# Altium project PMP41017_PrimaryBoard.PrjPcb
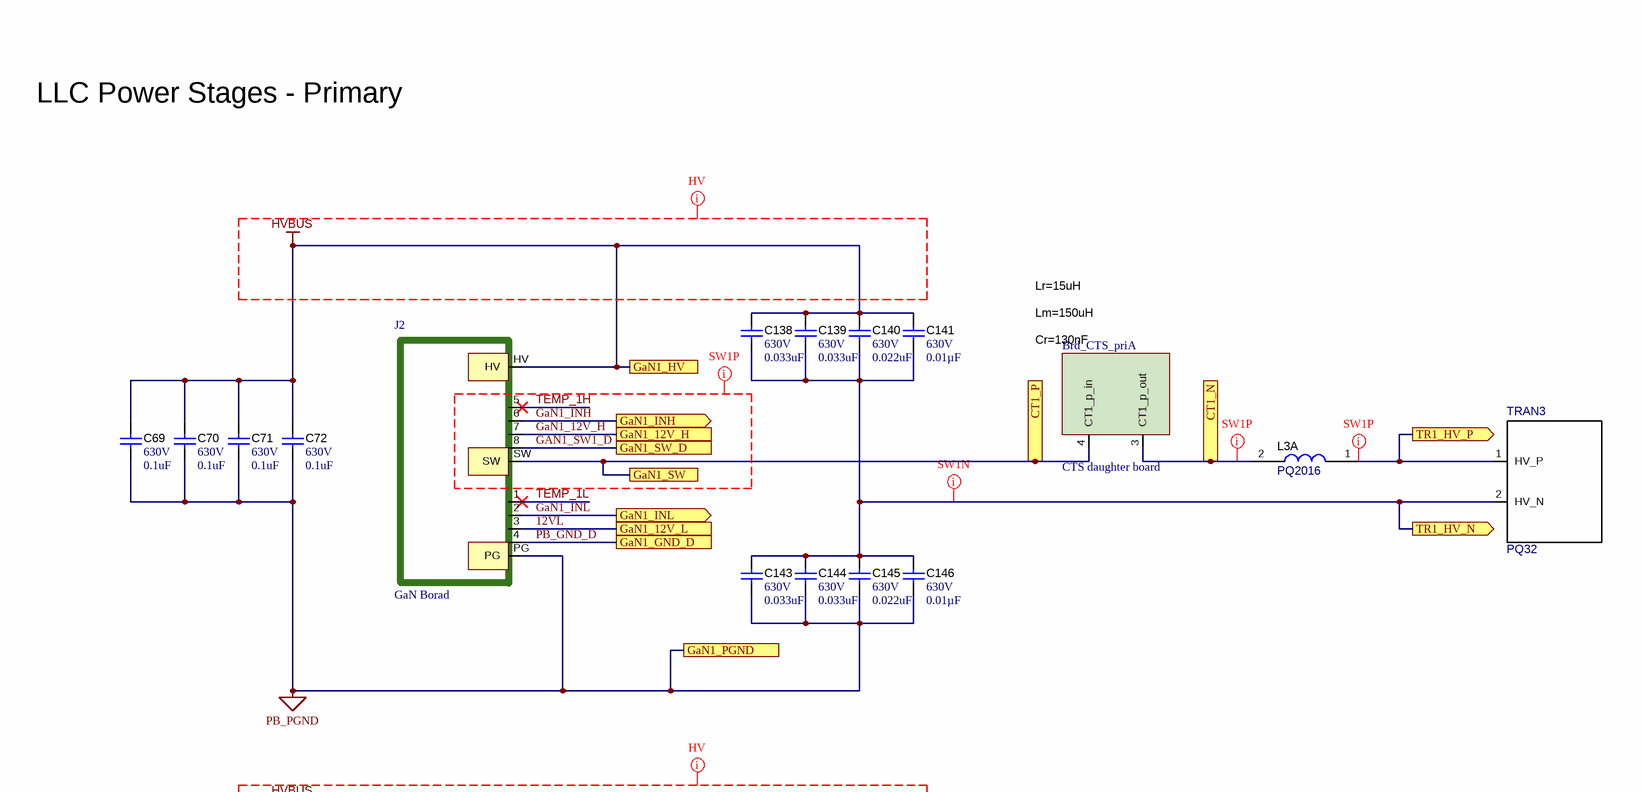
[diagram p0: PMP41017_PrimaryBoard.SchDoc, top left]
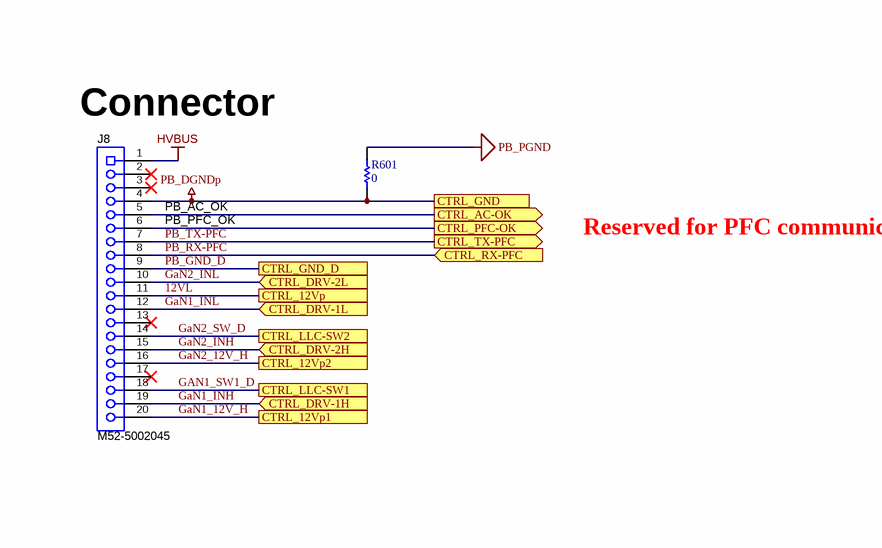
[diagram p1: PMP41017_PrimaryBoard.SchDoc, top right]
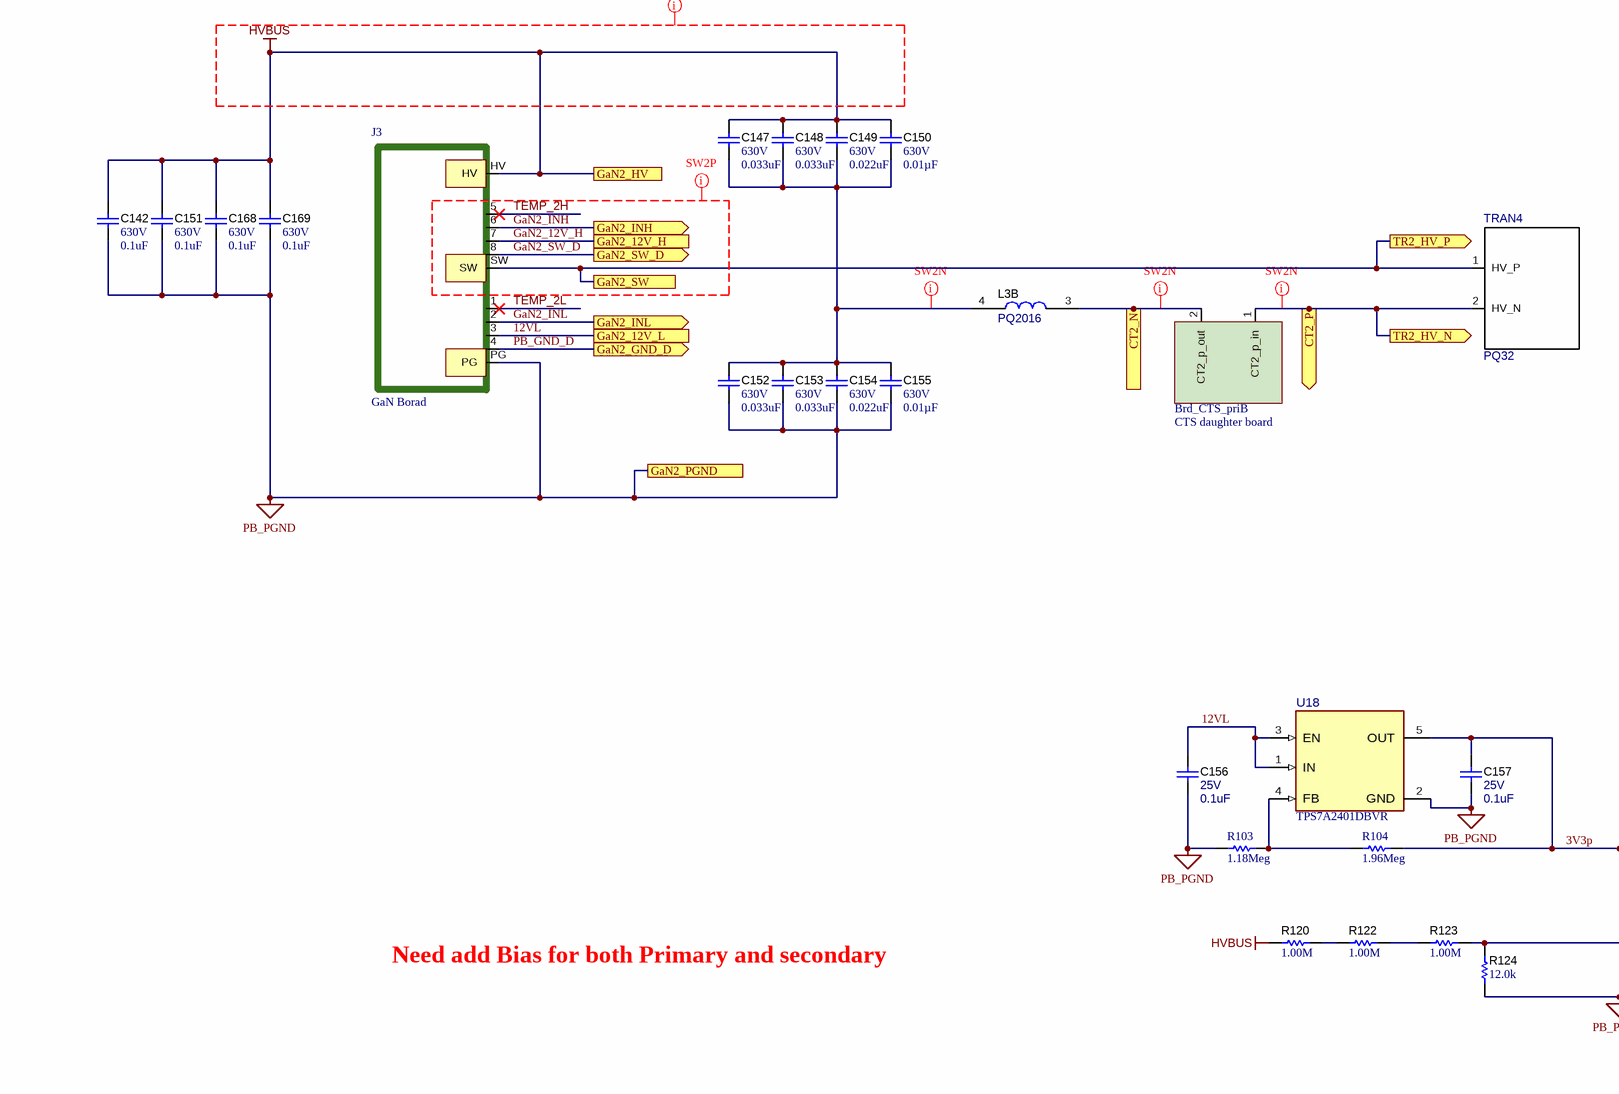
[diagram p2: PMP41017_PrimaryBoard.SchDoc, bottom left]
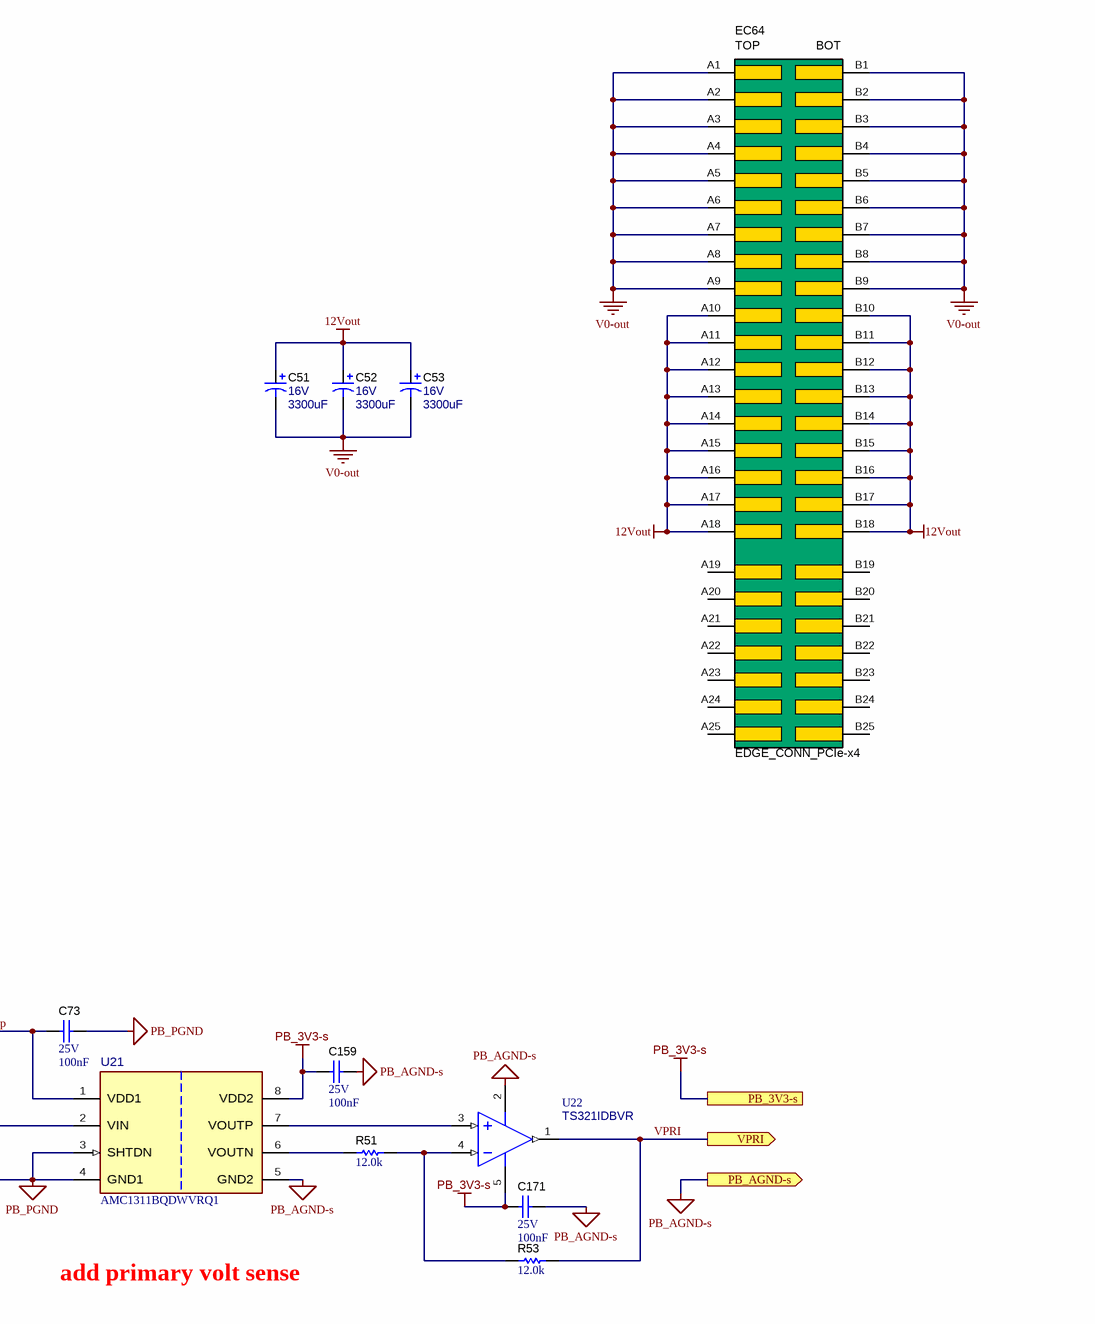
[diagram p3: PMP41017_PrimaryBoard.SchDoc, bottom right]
CopyrightYear: 2022; PCB_Layout: Desheng Guo; PCB_Rev: E1; PRJ_Customer: Public Release; PRJ_Engineer: Desheng Guo; PRJ_Number: PMP41017; PRJ_Title: CRPS 12V 3000W LLC; SCH_Rev: E1; TechSupport: http://www.ti.com/support; TID: N/A
1 sheet, 52 parts. Net scope: flat (ports and power ports of the same name join across sheets).
Board file: PMP41017_PrimaryBoard_Cyntec.PcbDoc

## Sheet PMP41017_PrimaryBoard.SchDoc
size A2; Date: Not shown in title block; ApprovedBy: Not shown in title block; CheckedBy: Not shown in title block; Author: Not shown in title block; CompanyName: Not shown in title block; Engineer: Not shown in title block; Organization: Not shown in title block; Address1: Not shown in title block; Address2: Not shown in title block; Address3: Not shown in title block; Address4: Not shown in title block; DocumentNumber: 1; Revision: Use project parameter SCH_Rev; SheetNumber: 1; SheetTotal: 1; PageSetup: Record=PageOptions¦CenterHorizontal=True¦CenterVertical=True¦PrintScale=0.69¦XCorrection=1.00¦YCorrection=1.00¦PrintKind=0¦BorderSize=5000000¦LeftOffset=0¦BottomOffset=0¦Orientation=2¦PaperLength=1000¦PaperWidth=1000¦Scale=100¦PaperSource=15¦PrintQuality=600¦MediaType=1¦DitherType=10¦PaperKind=Letter¦PrintScaleMode=1

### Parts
Brd_CTS_pri  CTS daughter board  [DB_PMP41017_CST]  (parts A,B of 2)
C51  VDC_V: 16V  ValueDisplayed: 3300uF  [860020378023]  (hidden comment: 860020378023)
C52  VDC_V: 16V  ValueDisplayed: 3300uF  [860020378023]  (hidden comment: 860020378023)
C53  VDC_V: 16V  ValueDisplayed: 3300uF  [860020378023]  (hidden comment: 860020378023)
C69  VDC_V: 630V  ValueDisplayed: 0.1uF  [1210_200]  (hidden comment: CGA6L1X7T2J104K160AC)
C70  VDC_V: 630V  ValueDisplayed: 0.1uF  [1210_200]  (hidden comment: CGA6L1X7T2J104K160AC)
C71  VDC_V: 630V  ValueDisplayed: 0.1uF  [1210_200]  (hidden comment: CGA6L1X7T2J104K160AC)
C72  VDC_V: 630V  ValueDisplayed: 0.1uF  [1210_200]  (hidden comment: CGA6L1X7T2J104K160AC)
C73  VDC_V: 25V  Cap_F: 100nF  [0603]  (hidden comment: GCM188R71E104KA57D)
C138  VDC_V: 630V  ValueDisplayed: 0.033uF  [1210_280]  (hidden comment: C3225C0G2J333J250AA)
C139  VDC_V: 630V  ValueDisplayed: 0.033uF  [1210_280]  (hidden comment: C3225C0G2J333J250AA)
C140  VDC_V: 630V  ValueDisplayed: 0.022uF  [1210_250]  (hidden comment: CGA6N4NP02J223J230AA)
C141  VDC_V: 630V  ValueDisplayed: 0.01µF  [1210_150]  (hidden comment: CGA6J4C0G2J103J125AA)
C142  VDC_V: 630V  ValueDisplayed: 0.1uF  [1210_200]  (hidden comment: CGA6L1X7T2J104K160AC)
C143  VDC_V: 630V  ValueDisplayed: 0.033uF  [1210_280]  (hidden comment: C3225C0G2J333J250AA)
C144  VDC_V: 630V  ValueDisplayed: 0.033uF  [1210_280]  (hidden comment: C3225C0G2J333J250AA)
C145  VDC_V: 630V  ValueDisplayed: 0.022uF  [1210_250]  (hidden comment: CGA6N4NP02J223J230AA)
C146  VDC_V: 630V  ValueDisplayed: 0.01µF  [1210_150]  (hidden comment: CGA6J4C0G2J103J125AA)
C147  VDC_V: 630V  ValueDisplayed: 0.033uF  [1210_280]  (hidden comment: C3225C0G2J333J250AA)
C148  VDC_V: 630V  ValueDisplayed: 0.033uF  [1210_280]  (hidden comment: C3225C0G2J333J250AA)
C149  VDC_V: 630V  ValueDisplayed: 0.022uF  [1210_250]  (hidden comment: CGA6N4NP02J223J230AA)
C150  VDC_V: 630V  ValueDisplayed: 0.01µF  [1210_150]  (hidden comment: CGA6J4C0G2J103J125AA)
C151  VDC_V: 630V  ValueDisplayed: 0.1uF  [1210_200]  (hidden comment: CGA6L1X7T2J104K160AC)
C152  VDC_V: 630V  ValueDisplayed: 0.033uF  [1210_280]  (hidden comment: C3225C0G2J333J250AA)
C153  VDC_V: 630V  ValueDisplayed: 0.033uF  [1210_280]  (hidden comment: C3225C0G2J333J250AA)
C154  VDC_V: 630V  ValueDisplayed: 0.022uF  [1210_250]  (hidden comment: CGA6N4NP02J223J230AA)
C155  VDC_V: 630V  ValueDisplayed: 0.01µF  [1210_150]  (hidden comment: CGA6J4C0G2J103J125AA)
C156  VDC_V: 25V  ValueDisplayed: 0.1uF  [0603]  (hidden comment: C1608X7R1E104K080AA)
C157  VDC_V: 25V  ValueDisplayed: 0.1uF  [0603]  (hidden comment: C1608X7R1E104K080AA)
C159  VDC_V: 25V  Cap_F: 100nF  [0603]  (hidden comment: GCM188R71E104KA57D)
C168  VDC_V: 630V  ValueDisplayed: 0.1uF  [1210_200]  (hidden comment: CGA6L1X7T2J104K160AC)
C169  VDC_V: 630V  ValueDisplayed: 0.1uF  [1210_200]  (hidden comment: CGA6L1X7T2J104K160AC)
C171  VDC_V: 25V  Cap_F: 100nF  [0603]  (hidden comment: GCM188R71E104KA57D)
EC64  EDGE_CONN_PCIe-x4  [EC_10035388-102LF]  (no BOM)
J2  GaN Borad  [DB_PMP41017_GAN]  (no BOM)
J3  GaN Borad  [DB_PMP41017_GAN]  (no BOM)
J8  M52-5002045  [M52-5002045]  (no BOM)
L3  PQ2016  [CHOKE-PQ2016 - H]  (parts A,B of 2)
R51  ValueDisplayed: 12.0k  [0603]  (hidden comment: RC0603FR-0712KL)
R53  ValueDisplayed: 12.0k  [0603]  (hidden comment: RC0603FR-0712KL)
R103  value 1.18Meg  [0402]
R104  value 1.96Meg  [0402]
R120  ValueDisplayed: 1.00M  [1206]  (hidden comment: CRCW12061M00FKEA)
R122  ValueDisplayed: 1.00M  [1206]  (hidden comment: CRCW12061M00FKEA)
R123  ValueDisplayed: 1.00M  [1206]  (hidden comment: CRCW12061M00FKEA)
R124  ValueDisplayed: 12.0k  [0603]  (hidden comment: RC0603FR-0712KL)
R601  value 0  [0402]
TRAN3  PQ32  [PQ3220-1500-400V12V_pri]
TRAN4  PQ32  [PQ3220-1500-400V12V_pri]
U18  TPS7A2401DBVR  [DBV0005A-MFG]
U21  AMC1311BQDWVRQ1  [DWV0008A-MFG]
U22  TS321IDBVR  [DBV0005A_L]

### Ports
CT1_N (out), CT1_P (out), CT2_N (out), CT2_P (out), CTRL_12Vp, CTRL_12Vp1, CTRL_12Vp2, CTRL_AC-OK (out), CTRL_DRV-1H (in), CTRL_DRV-1L (in), CTRL_DRV-2H (in), CTRL_DRV-2L (in), CTRL_GND, CTRL_GND_D, CTRL_LLC-SW1, CTRL_LLC-SW2, CTRL_PFC-OK (out), CTRL_RX-PFC (in), CTRL_TX-PFC (out), GaN1_12V_H, GaN1_12V_L, GaN1_GND_D, GaN1_HV, GaN1_INH (out), GaN1_INL (out), GaN1_PGND, GaN1_SW, GaN1_SW_D, GaN2_12V_H, GaN2_12V_L, GaN2_GND_D (out), GaN2_HV, GaN2_INH (out), GaN2_INL (out), GaN2_PGND, GaN2_SW, GaN2_SW_D (out), PB_3V3-s, PB_AGND-s (out), TR1_HV_N (out), TR1_HV_P (out), TR2_HV_N (out), TR2_HV_P (out), VPRI (out)

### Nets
12Vout: C51.1(+) C52.1(+) C53.1(+) EC64.A10 EC64.A11 EC64.A12 EC64.A13 EC64.A14 EC64.A15 EC64.A16 EC64.A17 EC64.A18 EC64.B10 EC64.B11 EC64.B12 EC64.B13 EC64.B14 EC64.B15 EC64.B16 EC64.B17 EC64.B18
HVBUS: C69.1 C70.1 C71.1 C72.1 C138.1 C139.1 C140.1 C141.1 C142.1 C147.1 C148.1 C149.1 C150.1 C151.1 C168.1 C169.1 J2.HV J3.HV J8.1 R120.2 ; port GaN1_HV, port GaN2_HV
PB_3V3-s: C159.1 C171.1 U21.8(VDD2) U22.5(VCC+) ; port PB_3V3-s
PB_AGND-s: C159.2 C171.2 U21.5(GND2) U22.2(VCC-) ; port PB_AGND-s
PB_DGNDp: J8.4 R601.2 ; port CTRL_GND
PB_PGND: C69.2 C70.2 C71.2 C72.2 C73.2 C142.2 C143.2 C144.2 C145.2 C146.2 C151.2 C152.2 C153.2 C154.2 C155.2 C156.2 C157.2 C168.2 C169.2 J2.PG J3.PG R103.1 R124.1 R601.1 U18.2(GND) U21.3(SHTDN) U21.4(GND1) ; port GaN1_PGND, port GaN2_PGND
V0-out: C51.2(-) C52.2(-) C53.2(-) EC64.A1 EC64.A2 EC64.A3 EC64.A4 EC64.A5 EC64.A6 EC64.A7 EC64.A8 EC64.A9 EC64.B1 EC64.B2 EC64.B3 EC64.B4 EC64.B5 EC64.B6 EC64.B7 EC64.B8 EC64.B9
3V3p: C73.1 C157.1 R104.2 U18.5(OUT) U21.1(VDD1)  [project net 3V3p_1]
12VL: C156.1 J2.3 J3.3 J8.11 U18.1(IN) U18.3(EN) ; port GaN1_12V_L, port CTRL_12Vp, port GaN2_12V_L
CT1_N: Brd_CTS_pri.3(CT1_p_out) L3.2 ; port CT1_N
CT1_P: Brd_CTS_pri.4(CT1_p_in) J2.SW ; port GaN1_SW, port CT1_P
CT2_N: Brd_CTS_pri.2(CT2_p_out) L3.3 ; port CT2_N
CT2_P: Brd_CTS_pri.1(CT2_p_in) TRAN4.2(HV_N) ; port CT2_P, port TR2_HV_N
GaN1_12V_H: J2.7 J8.20 ; port GaN1_12V_H, port CTRL_12Vp1
GaN1_INH: J2.6 J8.19 ; port GaN1_INH, port CTRL_DRV-1H
GaN1_INL: J2.2 J8.12 ; port GaN1_INL, port CTRL_DRV-1L
GAN1_SW1_D: J2.8 J8.18 ; port CTRL_LLC-SW1, port GaN1_SW_D
GaN2_12V_H: J3.7 J8.16 ; port CTRL_12Vp2, port GaN2_12V_H
GaN2_INH: J3.6 J8.15 ; port CTRL_DRV-2H, port GaN2_INH
GaN2_INL: J3.2 J8.10 ; port CTRL_DRV-2L, port GaN2_INL
GaN2_SW: J3.SW TRAN4.1(HV_P) ; port GaN2_SW, port TR2_HV_P
GaN2_SW_D: J3.8 J8.14 ; port CTRL_LLC-SW2, port GaN2_SW_D
PB_AC_OK: J8.5 ; port CTRL_AC-OK
PB_GND_D: J2.4 J3.4 J8.9 ; port GaN1_GND_D, port CTRL_GND_D, port GaN2_GND_D
PB_PFC_OK: J8.6 ; port CTRL_PFC-OK
PB_RX-PFC: J8.8 ; port CTRL_RX-PFC
PB_TX-PFC: J8.7 ; port CTRL_TX-PFC
TEMP_1H: J2.5  [project net TEMP_1H_1]
TEMP_1L: J2.1  [project net TEMP_1L_1]
TEMP_2H: J3.5  [project net TEMP_2H_1]
TEMP_2L: J3.1  [project net TEMP_2L_1]
TR1_HV_N: C138.2 C139.2 C140.2 C141.2 C143.1 C144.1 C145.1 C146.1 TRAN3.2(HV_N) ; port TR1_HV_N
TR1_HV_P: L3.1 TRAN3.1(HV_P) ; port TR1_HV_P
VPRI: R53.1 U22.1(OUT) ; port VPRI
NetC147_2: C147.2 C148.2 C149.2 C150.2 C152.1 C153.1 C154.1 C155.1 L3.4
NetR51_1: R51.1 R53.2 U22.4(IN-)
NetR51_2: R51.2 U21.6(VOUTN)
NetR103_2: R103.2 R104.1 U18.4(FB)
NetR120_1: R120.1 R122.2
NetR122_1: R122.1 R123.2
NetR123_1: R123.1 R124.2 U21.2(VIN)
NetU21_7: U21.7(VOUTP) U22.3(IN+)

Not connected (* = marked no-connect by the designer): EC64 A19 A20 A21 A22 A23 A24 A25 B19 B20 B21 B22 B23 B24 B25; J8 2* 3* 13* 17*

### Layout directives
net class SW1P: CT1_N, GaN1_12V_H, GaN1_INH, GAN1_SW1_D, TEMP_1H, TR1_HV_P
net class SW1N: TR1_HV_N
net class HV: HVBUS
net class SW2P: GaN2_12V_H, GaN2_INH, GaN2_SW_D, TEMP_2H
net class SW2N: CT2_N, CT2_P, NetC147_2

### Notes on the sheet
- (near J8) Connector
- LLC Power Stages - Primary
- Reserved for PFC communication
- Lm=150uH
- Lr=15uH
- Cr=130nF
- Need add Bias for both Primary and secondary
- add primary volt sense

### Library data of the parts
Brd_CTS_pri = Board_CTS
C51-C53 = Cap_Polarized_1: CAP, AL, 3300 uF, 16 V, +/- 20%, 0.023 ohm, TH; Manufacturer: Würth Elektronik; TaMin_C: -40°C; ESR_ohm: 0.034; Polarized: Y; SizeAreaWB_mm2: 324; Value1: 0.034 ohm; U/M: EA; Value: 3300uF; TaMax_C: 105°C; SizeZ_mm: 33.5; SizeX_mm: 13; Cap_Case: 13x25mm; SizeArea_mm2: 256; CompType: Capacitor; Cap_F: 3.3mF; IRMS_A: 3.16A; AEC Grade: 1; AEC Category: Q200
C69-C72 C142 C151 C168 C169 = CMP-0009140-2: CAP, CERM, 0.1 uF, 630 V, +/- 10%, X7R, AEC-Q200 Grade 1, 1210; Manufacturer: TDK; TaMin_C: -55°C; Polarized: N; SizeAreaWB_mm2: 14.7; Value1: Unknown; U/M: EA; Value: 0.1uF; TaMax_C: 125°C; SizeZ_mm: 2; SizeX_mm: 3.2; SizeY_mm: 2.5; Cap_Case: 1210; SizeArea_mm2: 8; AEC Qualified: Y; Cap_F: 100nF; AEC Grade: 1; AEC Category: Q200
C73 C159 C171 = CMP-0084679-1: CAP, CERM, 0.1 µF, 25 V,+/- 10%, X7R, AEC-Q200 Grade 1, 0603; Manufacturer: MuRata; TaMin_C: -55°C; SizeY_mm: 0.8; Polarized: N; SizeArea_mm2: 1.28; SizeZ_mm: 1; SizeX_mm: 1.6; AEC Qualified: Y; AEC Category: Q200; Value: 0.1uF; ValueDisplayed: 0.1µF; TaMax_C: 125°C; U/M: EA; SizeAreaWB_mm2: 4.68
C138 C139 C143 C144 C147 C148 C152 C153 = CMP-0009097-2: CAP, CERM, 0.033 uF, 630 V, +/- 5%, C0G/NP0, 1210; Manufacturer: TDK; TaMin_C: -55°C; Polarized: N; SizeAreaWB_mm2: 14.7; Value1: Unknown; U/M: EA; TaMax_C: 125°C; SizeZ_mm: 2.8; SizeX_mm: 3.2; SizeY_mm: 2.5; Cap_Case: 1210; SizeArea_mm2: 8; Cap_F: 33nF; AEC Category: Q200
C140 C145 C149 C154 = CMP-0009153-2: CAP, CERM, 0.022 uF, 630 V, +/- 5%, C0G/NP0, AEC-Q200 Grade 0,; Manufacturer: TDK; TaMin_C: -55°C; Polarized: N; SizeAreaWB_mm2: 14.7; Value1: Unknown; U/M: EA; TaMax_C: 150°C; SizeZ_mm: 2.5; SizeX_mm: 3.2; Cap_Case: 1210; SizeArea_mm2: 8; AEC Qualified: Y; Cap_F: 22nF; AEC Grade: 0; AEC Category: Q200
C141 C146 C150 C155 = CMP-0860380-1: CAP, CERM, 0.01 µF, 630 V,+/- 5%, C0G/NP0, AEC-Q200 Grade 1, 1210; Manufacturer: TDK; AEC Qualified: Y; Polarized: N; SizeZ_mm: 1.5; SizeArea_mm2: 8; U/M: EA; SizeX_mm: 3.2; SizeY_mm: 2.5; Cap_F: 10nF; SizeAreaWB_mm2: 14.7; TaMin_C: -55°C; Cap_Case: 1210; Value: 0.01uF; AEC Grade: 1; TaMax_C: 125°C; AEC Category: Q200
C156 C157 = CMP-0007039-5: CAP, CERM, 0.1 uF, 25 V, +/- 10%, X7R, 0603; Manufacturer: TDK; TaMin_C: -55°C; Polarized: N; SizeAreaWB_mm2: 4.68; Value1: Unknown; U/M: EA; Value: 0.1uF; TaMax_C: 125°C; SizeZ_mm: 1; SizeX_mm: 1.6; SizeY_mm: 0.8; SizeArea_mm2: 1.28; Cap_F: 100nF; AEC Category: Q200
EC64 = EDGE_CONN_CRPS: Card Edge Footprint for CRPS Server PSU, 2.54mm, 25x2; Manufacturer: Texas Instruments
J2 J3 = Brd_GaN_footprint
J8 = Receptacle_20x1: Receptacle, 20x1, 1.27mm, TH; Manufacturer: Harwin Inc.; CT: False; CompType: Socket
L3 = INDUCTOR_COUPLED: Customized Resonant Choke; Manufacturer: YAXIN ELECTRONIC TECH; PartNumber: YXS50494T; DCR_ohm: 0.019; CompType: Coupled Inductor; Ind_H: 13uH; SizeX_mm: 22; SizeY_mm: 10; SizeZ_mm: 16
R51 R53 R124 = CMP-0022779-5: RES, 12.0 k, 1%, 0.1 W, 0603; Manufacturer: Yageo; Power_W: 100mW; TempCo: 100 ppm/C; Value_Code: 12k0; Value: 12.0k; Res_ohm: 12k; SizeX_mm: 1.6; SizeY_mm: 0.8; SizeZ_mm: 1; Value2: 0.1W; SizeArea_mm2: 1.28; AEC Qualified: N; VDC_V: 75V; AEC Category: Q200; SizeAreaWB_mm2: 4.68
R103 = Res1: RES, 1.18Meg, 1%, 0.1 W, 0402
R104 = Res1: RES, 1.96Meg, 1%, 0.1 W, 0402
R120 R122 R123 = CMP-0016716-3: RES, 1.00 M, 1%, 0.25 W, AEC-Q200 Grade 0, 1206; Manufacturer: Vishay-Dale; Power_W: 250mW; TempCo: 100 ppm/C; Value_Code: 1M00; Value: 1.00Meg; EIA_Code: E96; Res_ohm: 1M; SizeX_mm: 3.2; SizeY_mm: 1.6; SizeZ_mm: 1.35; Value2: 0.25W; SizeArea_mm2: 5.12; AEC Qualified: Y; VDC_V: 200V; AEC Category: Q200; AEC Grade: 0
R601 = Res1: RES, 0, 5%, 0.1 W, AEC-Q200 Grade 0, 0402
TRAN3 TRAN4 = Transformer_pri: PQ32 TRANSFORMER; Manufacturer: YAXIN ELECTRONIC TECH; SymbolCreator: Use LDAP id; SymbolVersion: use current date i.e. 2008-05-20
U18 = CMP-0089843-1: Linear Voltage Regulator IC 1 Output 200mA SOT-23-5; Manufacturer: Texas Instruments; Output Type: AdjustableProgrammable; Accuracy Percentage: 2%; AEC Qualified: No; Max Supply Voltage: 18V; Dropout Voltage: 160mV; SizeZ_mm: 1.45mm; Output Voltage: 1.24-17.75V; Min Supply Voltage: 2.4V; TJmax_C: +125°C; Nominal Supply Current: 2uA; Number Of Outputs: 1; Standoff Height: 0mm
U21 = CMP-0090465-1: Automotive 2-V input, reinforced isolated amplifier with high CMTI for voltage sensing 8-SOIC -40 to 125; Manufacturer: Texas Instruments; Input Offset Voltage: -1.1mV; Response Time: 50us; Standoff Height: 0.36mm; Nominal Supply Current: 5.3-7.1mA; AEC Grade: Grade 1; Number Of Channels: 1; TJmax_C: +150°C; AEC Qualified: Yes; Max Supply Voltage: 5.5V; SizeZ_mm: 2.8mm; Input Bias Current: 0.0035uA; TaMax_C: +125°C; TaMin_C: -40°C; Output Current Per Channel: 13mA; Min Supply Voltage: 3V; Bandwidth: 275kHz
U22 = CMP-0043733-1: Low-Power Single Operational Amplifier, 3 to 30 V, -40 to 125 degC, 5-pin SOT23 (DBV5), Green (RoHS & no Sb/Br); Manufacturer: Texas Instruments; Iq per channel(Max)(mA): 1; Sub Family: General Purpose Amplifier, High Supply Voltage Amplifier (>=30V); CMRR(Min)(dB): 65; Total Supply Voltage(Max)(+5V is 5, +/-5V is 10): 30; Slew Rate(Typ)(V/us): 0.4; Vio (25C)(Max)(mV): 4; GBW(Typ)(MHz): 0.8; IIB(Max)(pA): 200000; Vn at 1kHz(Typ)(nV/rtHz): 50; Total Supply Voltage(Min)(+5V is 5, +/-5V is 10): 3

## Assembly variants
001: not fitted FID1 FID2 FID3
